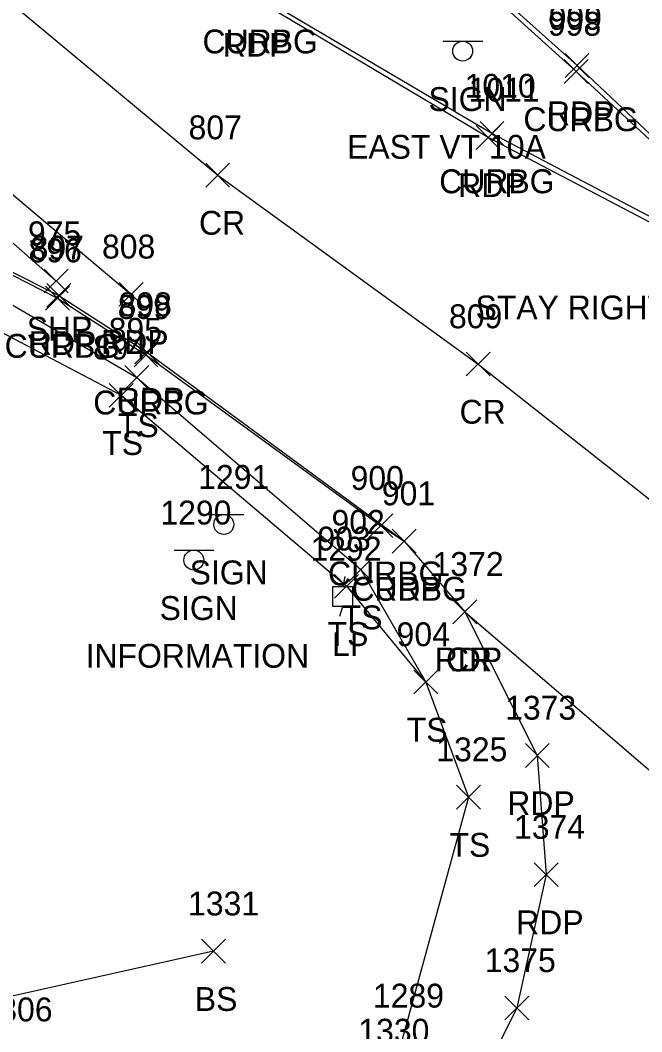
# Model space of a CAD drawing. Extents: x 1688195 to 1692013, y 424605 to 441234.
# Drawn here: x 1691850.9 to 1691903, y 439158.5 to 439243.2 of the extents above; entities that cross this region are included whole.
import ezdxf

# ---------------------------------------------------------------- set-up
doc = ezdxf.new("R2010")
doc.units = 0
for name, color, linetype in [('L_A', 7, 'Continuous'), ('L_I', 7, 'Continuous'), ('L_TIC', 7, 'Continuous'), ('LELB', 7, 'Continuous'), ('P_A', 7, 'Continuous'), ('P_I', 7, 'Continuous'), ('P_TIC', 7, 'Continuous'), ('PET', 7, 'Continuous'), ('PRC', 7, 'Continuous'), ('PSP', 7, 'Continuous'), ('R_A', 7, 'Continuous'), ('R_I', 7, 'Continuous'), ('R_TIC', 7, 'Continuous'), ('RC', 7, 'Continuous'), ('S_A', 7, 'Continuous'), ('S_C', 7, 'Continuous'), ('S_I', 7, 'Continuous'), ('SSGN', 7, 'Continuous'), ('U_A', 7, 'Continuous'), ('U_I', 7, 'Continuous'), ('ULP', 7, 'Continuous')]:
    doc.layers.add(name, color=color, linetype=linetype)

msp = doc.modelspace()

# ---------------------------------------------------------------- linework, layer by layer
at = {"layer": 'L_TIC'}
for points in [[(1691859.674, 439212.285), (1691861.674, 439214.285)], [(1691861.674, 439212.285), (1691859.674, 439214.285)], [(1691858.36, 439210.797), (1691860.36, 439212.797)], [(1691860.36, 439210.797), (1691858.36, 439212.797)], [(1691878.413, 439196.187), (1691880.413, 439198.187)], [(1691880.413, 439196.187), (1691878.413, 439198.187)], [(1691877.234, 439194.791), (1691879.234, 439196.791)], [(1691879.234, 439194.791), (1691877.234, 439196.791)], [(1691883.864, 439186.773), (1691885.864, 439188.773)], [(1691885.864, 439186.773), (1691883.864, 439188.773)], [(1691883.864, 439186.773), (1691885.864, 439188.773)], [(1691885.864, 439186.773), (1691883.864, 439188.773)], [(1691887.44, 439177.127), (1691889.44, 439179.127)], [(1691889.44, 439177.127), (1691887.44, 439179.127)], [(1691866.083, 439164.211), (1691868.083, 439166.211)], [(1691868.083, 439164.211), (1691866.083, 439166.211)]]:
    msp.add_lwpolyline(points, dxfattribs=at)
at = {"layer": 'LELB'}
for points in [[(1691809.053, 439198.7), (1691810.068, 439220.423), (1691810.472, 439227.708), (1691810.037, 439233.748), (1691820.977, 439231.155), (1691837.253, 439226.413), (1691844.547, 439222.678), (1691860.674, 439213.285), (1691879.413, 439197.187), (1691884.864, 439187.773), (1691888.44, 439178.127), (1691882.001, 439154.551), (1691849.25, 439142.61), (1691815.325, 439128.47), (1691761.502, 439106.684), (1691722.867, 439092.032), (1691697.517, 439087.726), (1691657.954, 439070.386), (1691613.621, 439049.579), (1691576.983, 439020.144), (1691544.829, 438993.146), (1691508.196, 438954.885), (1691488.694, 438935.2)], [(1691810.472, 439227.708), (1691820.406, 439227.634), (1691836.548, 439222.635), (1691844.486, 439219.638), (1691859.36, 439211.797), (1691878.234, 439195.791), (1691884.864, 439187.773)], [(1691867.083, 439165.211), (1691844.953, 439160.267), (1691798.836, 439152.108), (1691745.507, 439147.112), (1691728.71, 439142.405), (1691709.094, 439133.879), (1691682.996, 439117.204), (1691643.276, 439091.076), (1691604.891, 439061.286), (1691572.531, 439026.723), (1691542.378, 438995.546), (1691505.845, 438957.496), (1691487.655, 438936.341), (1691466.81, 438915.543), (1691436.023, 438880.856), (1691415.553, 438858.764)]]:
    msp.add_lwpolyline(points, dxfattribs=at)
at = {"layer": 'P_TIC'}
for points in [[(1691896.532, 439238.425), (1691898.532, 439240.425)], [(1691898.532, 439238.425), (1691896.532, 439240.425)], [(1691889.09, 439232.403), (1691891.09, 439234.403)], [(1691891.09, 439232.403), (1691889.09, 439234.403)], [(1691866.441, 439229.247), (1691868.441, 439231.247)], [(1691868.441, 439229.247), (1691866.441, 439231.247)], [(1691852.912, 439220.372), (1691854.912, 439222.372)], [(1691854.912, 439220.372), (1691852.912, 439222.372)], [(1691859.192, 439219.256), (1691861.192, 439221.256)], [(1691861.192, 439219.256), (1691859.192, 439221.256)], [(1691853.138, 439219.168), (1691855.138, 439221.168)], [(1691855.138, 439219.168), (1691853.138, 439221.168)], [(1691860.506, 439214.423), (1691862.506, 439216.423)], [(1691862.506, 439214.423), (1691860.506, 439216.423)], [(1691888.259, 439213.415), (1691890.259, 439215.415)], [(1691890.259, 439213.415), (1691888.259, 439215.415)], [(1691882.06, 439198.579), (1691884.06, 439200.579)], [(1691884.06, 439198.579), (1691882.06, 439200.579)], [(1691887.13, 439192.66), (1691889.13, 439194.66)], [(1691889.13, 439192.66), (1691887.13, 439194.66)], [(1691887.13, 439192.66), (1691889.13, 439194.66)], [(1691889.13, 439192.66), (1691887.13, 439194.66)], [(1691893.204, 439180.616), (1691895.204, 439182.616)], [(1691895.204, 439180.616), (1691893.204, 439182.616)], [(1691893.95, 439170.633), (1691895.95, 439172.633)], [(1691895.95, 439170.633), (1691893.95, 439172.633)], [(1691891.497, 439159.46), (1691893.497, 439161.46)], [(1691893.497, 439159.46), (1691891.497, 439161.46)]]:
    msp.add_lwpolyline(points, dxfattribs=at)
at = {"layer": 'PET'}
for points in [[(1691703.519, 439378.215), (1691727.927, 439348.964), (1691752.514, 439320.765), (1691774.827, 439296.788), (1691803.993, 439267.935), (1691829.698, 439246.009), (1691860.192, 439220.256)], [(1691800.945, 439315.05), (1691800.709, 439316.533), (1691801.542, 439317.586), (1691803.007, 439317.751), (1691817.064, 439309.697), (1691828.512, 439300.647), (1691844.684, 439285.422), (1691865.174, 439267.394), (1691884.848, 439250.831), (1691897.532, 439239.425), (1691910.299, 439227.429), (1691911.518, 439225.273), (1691910.888, 439223.79), (1691909.812, 439223.418), (1691908.764, 439223.597), (1691890.09, 439233.403), (1691870.381, 439245.165), (1691862.377, 439250.392), (1691860.033, 439251.797), (1691851.002, 439258.938), (1691829.097, 439279.042), (1691821.385, 439286.908), (1691810.775, 439300.426)], [(1691715.714, 439221.672), (1691737.082, 439230.055), (1691750.128, 439233.775), (1691763.328, 439236.221), (1691779.804, 439237.901), (1691792.46, 439237.573), (1691804.318, 439236.191), (1691808.491, 439235.452), (1691812.042, 439235.195), (1691821.483, 439233.162), (1691827.737, 439231.575), (1691835.045, 439229.097), (1691845.28, 439224.601), (1691854.138, 439220.168), (1691861.506, 439215.423), (1691883.06, 439199.579), (1691888.13, 439193.66), (1691894.204, 439181.616), (1691894.95, 439171.633), (1691892.497, 439160.46), (1691888.634, 439152.728)]]:
    msp.add_lwpolyline(points, dxfattribs=at)
at = {"layer": 'PRC'}
for points in [[(1691713.182, 439386.477), (1691737.313, 439357.714), (1691761.172, 439330.745), (1691784.31, 439305.517), (1691812.134, 439278.202), (1691838.297, 439254.51), (1691867.441, 439230.247), (1691889.259, 439214.415), (1691920.444, 439189.798), (1691954.552, 439163.68)], [(1691888.13, 439193.66), (1691921.534, 439164.988), (1691933.606, 439155.104), (1691905.33, 439143.804), (1691864.7, 439127.178), (1691822.777, 439112.303), (1691787.262, 439099.583), (1691756.919, 439088.304), (1691729.193, 439077.852), (1691704.029, 439068.301), (1691667.699, 439053.497), (1691645.705, 439043.492), (1691628.457, 439034.88), (1691608.734, 439022.918), (1691585.224, 439006.395), (1691574.918, 438998.748), (1691559.839, 438985.929), (1691543.5, 438970.756), (1691518.613, 438946.021), (1691478.272, 438903.206), (1691447.81, 438869.999), (1691426.937, 438847.449)]]:
    msp.add_lwpolyline(points, dxfattribs=at)
at = {"layer": 'PSP'}
msp.add_lwpolyline([(1691696.132, 439372.686), (1691709.548, 439355.191), (1691723.603, 439339.325), (1691742.747, 439319), (1691750.974, 439309.526), (1691763.384, 439297.713), (1691773.94, 439286.942), (1691807.317, 439260.152), (1691827.219, 439244.924), (1691853.912, 439221.372)], dxfattribs=at)
at = {"layer": 'R_TIC'}
for points in [[(1691896.458, 439237.929), (1691898.458, 439239.929)], [(1691898.458, 439237.929), (1691896.458, 439239.929)], [(1691889.407, 439232.729), (1691891.407, 439234.729)], [(1691891.407, 439232.729), (1691889.407, 439234.729)], [(1691853.015, 439218.94), (1691855.015, 439220.94)], [(1691855.015, 439218.94), (1691853.015, 439220.94)], [(1691860.435, 439214.191), (1691862.435, 439216.191)], [(1691862.435, 439214.191), (1691860.435, 439216.191)], [(1691880.097, 439199.869), (1691882.097, 439201.869)], [(1691882.097, 439199.869), (1691880.097, 439201.869)], [(1691882.06, 439198.579), (1691884.06, 439200.579)], [(1691884.06, 439198.579), (1691882.06, 439200.579)]]:
    msp.add_lwpolyline(points, dxfattribs=at)
at = {"layer": 'RC'}
for points in [[(1691801.246, 439315.044), (1691801.115, 439316.331), (1691801.764, 439317.377), (1691802.82, 439317.349), (1691816.869, 439309.413), (1691828.254, 439300.3), (1691844.418, 439285.107), (1691865.016, 439267.121), (1691884.737, 439250.475), (1691897.458, 439238.929), (1691910.163, 439227.134), (1691911.269, 439225.368), (1691910.647, 439224.032), (1691909.839, 439223.784), (1691908.933, 439223.978), (1691890.407, 439233.729), (1691870.585, 439245.445), (1691863.213, 439250.357), (1691862.377, 439250.392)], [(1691808.491, 439235.452), (1691812.009, 439234.868), (1691821.363, 439233.003), (1691827.722, 439231.205), (1691834.697, 439228.878), (1691845.197, 439224.436), (1691854.015, 439219.94), (1691861.435, 439215.191), (1691881.097, 439200.869), (1691883.06, 439199.579)]]:
    msp.add_lwpolyline(points, dxfattribs=at)
at = {"layer": 'SSGN'}
for p, q in [((1691886.309, 439241.471), (1691889.643, 439241.471)), ((1691887.956, 439240.638), (1691887.956, 439240.638)), ((1691866.305, 439201.809), (1691869.639, 439201.809)), ((1691867.952, 439200.975), (1691867.952, 439200.975)), ((1691863.795, 439198.823), (1691867.128, 439198.823)), ((1691865.441, 439197.99), (1691865.441, 439197.99))]:
    msp.add_line(p, q, dxfattribs=at)
for centre in [(1691887.956, 439240.638), (1691867.952, 439200.975), (1691865.441, 439197.99)]:
    msp.add_circle(centre, 0.833, dxfattribs=at)
at = {"layer": 'ULP'}
for p, q in [((1691878.074, 439196.61), (1691877.907, 439195.776)), ((1691877.074, 439194.11), (1691877.074, 439195.776)), ((1691877.074, 439195.776), (1691878.741, 439195.776)), ((1691878.741, 439195.776), (1691878.741, 439194.11)), ((1691878.741, 439194.11), (1691877.074, 439194.11)), ((1691877.657, 439193.276), (1691877.907, 439194.11)), ((1691877.907, 439194.943), (1691877.907, 439194.943))]:
    msp.add_line(p, q, dxfattribs=at)

# ---------------------------------------------------------------- texts
at = {"layer": 'L_A'}
for s, p in [('TS', (1691859.083, 439208.285)), ('TS', (1691857.77, 439206.797)), ('TS', (1691877.823, 439192.187)), ('TS', (1691876.643, 439190.791)), ('TS', (1691883.274, 439182.773)), ('TS', (1691883.274, 439182.773)), ('TS', (1691886.85, 439173.127)), ('BS', (1691865.524, 439160.211))]:
    msp.add_text(s, height=2, dxfattribs=at).set_placement(p)
at = {"layer": 'L_I'}
for s, p in [('895', (1691858.312, 439216.285)), ('894', (1691856.998, 439214.797)), ('902', (1691876.973, 439200.187)), ('903', (1691875.793, 439198.791)), ('904', (1691882.423, 439190.773)), ('904', (1691882.423, 439190.773)), ('1325', (1691885.747, 439181.127)), ('1331', (1691864.957, 439168.211)), ('1330', (1691879.221, 439157.551))]:
    msp.add_text(s, height=2, dxfattribs=at).set_placement(p)
at = {"layer": 'P_A'}
for s, p in [('RDP', (1691867.869, 439240.165)), ('RDP', (1691895.02, 439234.425)), ('RDP', (1691887.578, 439228.403)), ('CR', (1691865.874, 439225.247)), ('SHP', (1691851.447, 439216.372)), ('RDP', (1691851.626, 439215.168)), ('RDP', (1691857.68, 439215.256)), ('RDP', (1691858.994, 439210.423)), ('CR', (1691887.692, 439209.415)), ('RDP', (1691880.548, 439194.579)), ('RDP', (1691885.618, 439188.66)), ('CR', (1691886.563, 439188.66)), ('RDP', (1691891.692, 439176.616)), ('RDP', (1691892.438, 439166.633))]:
    msp.add_text(s, height=2, dxfattribs=at).set_placement(p)
at = {"layer": 'P_I'}
for s, p in [('999', (1691895.162, 439242.425)), ('1011', (1691888.452, 439236.403)), ('807', (1691865, 439233.247)), ('975', (1691851.55, 439224.372)), ('897', (1691851.776, 439223.168)), ('808', (1691857.751, 439223.256)), ('898', (1691859.144, 439218.423)), ('809', (1691886.81, 439217.415)), ('901', (1691881.186, 439202.579)), ('1372', (1691885.437, 439196.66)), ('1372', (1691885.437, 439196.66)), ('1373', (1691891.511, 439184.616)), ('1374', (1691892.257, 439174.633)), ('1375', (1691889.804, 439163.46))]:
    msp.add_text(s, height=2, dxfattribs=at).set_placement(p)
at = {"layer": 'R_A'}
for p in [(1691866.168, 439240.445), (1691893.041, 439233.929), (1691885.99, 439228.729), (1691849.598, 439214.94), (1691857.018, 439210.191), (1691876.68, 439195.869), (1691878.643, 439194.579)]:
    msp.add_text('CURBG', height=2, dxfattribs=at).set_placement(p)
at = {"layer": 'R_I'}
for s, p in [('998', (1691895.096, 439241.929)), ('1010', (1691888.116, 439236.729)), ('896', (1691851.598, 439222.94)), ('899', (1691859.065, 439218.191)), ('900', (1691878.57, 439203.869)), ('901', (1691881.186, 439202.579))]:
    msp.add_text(s, height=2, dxfattribs=at).set_placement(p)
at = {"layer": 'S_A'}
for p in [(1691885.094, 439235.618), (1691865.09, 439195.955), (1691862.579, 439192.969)]:
    msp.add_text('SIGN', height=2, dxfattribs=at).set_placement(p)
at = {"layer": 'S_C'}
for s, p in [('EAST VT 10A', (1691878.275, 439231.618)), ('STAY RIGHT OF MEDIAN', (1691889.03, 439218.154)), ('INFORMATION', (1691856.375, 439188.969))]:
    msp.add_text(s, height=2, dxfattribs=at).set_placement(p)
at = {"layer": 'S_I'}
for s, p in [('1291', (1691865.807, 439203.955)), ('1290', (1691862.642, 439200.969)), ('1289', (1691880.441, 439160.491))]:
    msp.add_text(s, height=2, dxfattribs=at).set_placement(p)
at = {"layer": 'U_A'}
msp.add_text('LI', height=2, dxfattribs=at).set_placement((1691877.01, 439189.943))
at = {"layer": 'U_I'}
for s, p in [('1292', (1691875.214, 439197.943)), ('1306', (1691847.661, 439159.336))]:
    msp.add_text(s, height=2, dxfattribs=at).set_placement(p)

doc.saveas('drawing.dxf')
